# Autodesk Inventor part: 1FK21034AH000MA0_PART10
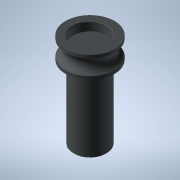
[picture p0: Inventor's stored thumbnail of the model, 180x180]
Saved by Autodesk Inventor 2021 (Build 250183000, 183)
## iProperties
Created: 2025-04
Part Number: 1FK21034AH000MA0_PART10
Material: Generic
Catalog Web Link: www.3dfindit.com
Description: -Servo synchronous motor
Document SubType Name: Modeling
Designer: psAdmin
Mass: 6.43867 g
Surface Area: 29.6592 cm^2
Volume: 6.43867 cm^3
Density: 1 g/cm^3
Appearance: PSOLRGB-212-217-219
Category: PARTsolutions
Title: 1FK21034AH000MA0_PART10
Author: Cadenas PARTsolutions
Comments: Servo synchronous motor
Sending System: PARTsolutions
Preprocessor: ST-DEVELOPER v19.3
PSOL_IDENT_0: {$CADENAS_DATA/23d-libs/siemens_ag/_cat_/ec/b7/1fk21034ah000ma0.prj},216 {VTYP=3D},{NB=1FK21034AH000
PSOL_IDENT_1: MA0_PART10},{LINA=1FK21034AH000MA0_PART10},{NN=1FK21034AH000MA0_PART10},{NOPRJ=TRUE},{DATE=19.08.202
PSOL_IDENT_2: 5 14:01:05},{GEOMDATE=30.07.2025 02:01:02},{VERSION=},{LINEID=10},{WBVAR=},{WBNUMERIC=}  {NB=1FK2103
PSOL_IDENT_3: 4AH000MA0_PART10},{LINA=1FK21034AH000MA0_PART10},{KT=DUMMY},{PREVIEW=../../../_pool_/7c/50/p_d211_xx
PSOL_IDENT_4: _00932j.png},{DESCSHORT=SIMOTICS S-1FK2 HD, SINAMICS S210 3AC 400V-480V, 1.01 Nm, 4500 rpm},{DESCLON
PSOL_IDENT_5: G=SIMOTICS S-1FK2 HD servo motor M0=1.27 Nm; PN = 0.48 kW at nN=4500 rpm (380-480 V); PN = 0.3 kW at
PSOL_IDENT_6: nN=2500 rpm (200-240 V); degree of protection IP64; cylindrical shaft D14 x 30 mm; absolute encoder
PSOL_IDENT_7: 22-bit + 12-bit multiturn (encoder AM22DQC); with OCC interface; plug size M17, rotatable; SIMOTICS
PSOL_IDENT_8: S-1FK2 servomotorfor a wide range of uses in industrial environments. SIMOTICS S‑1FK2 servomotors a
PSOL_IDENT_9: re compact synchronous motors with a high dynamic performance that set themselves apart as a result
PSOL_IDENT_10: of their high power density, degree of protection and overload capability. The motors are available
PSOL_IDENT_11: in two variants: as High Dynamic variant (highest dynamic performance as a result of the low intrins
PSOL_IDENT_12: ic moment of inertia for applications demanding a high dynamic performance with low moved masses) -
PSOL_IDENT_13: and as Compact variant (precise and stable closed-loop control for medium up to large moved masses a
PSOL_IDENT_14: s a result of a medium intrinsic moment of inertia). SIMOTICSS‑1FK2 servomotors fully exploit their
PSOL_IDENT_15: strengths in a system with the SINAMICSS210 frequency converter and simple connection using the one
PSOL_IDENT_16: cable connection (OCC). Advantages include the short control and positioning times, fast and precise
PSOL_IDENT_17: correction of disturbing quantities as well as stable control with a high dynamic performance. The
PSOL_IDENT_18: servo motors can be configured to address a wide range of requirements. For example with and without
PSOL_IDENT_19: holding brake, IP64 or IP65 degree of protection, singleturn or multiturn absolute encoders - to na
PSOL_IDENT_20: me just a few. Further, the servomotors are available in different shaft heights extending from 20 t
PSOL_IDENT_21: o 100. A shaft sealing ring is available to achieve an IP65 degree of protection and for subsequent
PSOL_IDENT_22: mounting at the motor or as spare part. SIMOTICS - the optimum motor for each and every motion contr
PSOL_IDENT_23: ol application.},{INTNO=4034106444822},{SUPPLIERALTNO=1FK2103-4AH00-0MA0},{MANUID=1FK21034AH000MA0},
PSOL_IDENT_24: {MANUNAME=Siemens},{MANUTYPEDESC=SYNCHRONOUS MOTOR 1FK2 HD 1,27 NM},{AAU732=SIMOTICS},{AAO057=S-1FK2
PSOL_IDENT_25: },{AAU734=SIMOTICS S-1FK2 HD servo motor M0=1.27 Nm; PN = 0.48 kW at nN=4500 rpm (380-480 V); PN = 0
PSOL_IDENT_26: .3 kW at nN=2500 rpm (200-240 V); degree of protection IP64; cylindrical shaft D14 x 30 mm; absolute
PSOL_IDENT_27: encoder 22-bit + 12-bit multiturn (encoder AM22DQC); with OCC interface; plug size M17, rotatable;}
PSOL_IDENT_28: ,{AAW338=SYNCHRONOUS MOTOR 1FK2 HD 1,27 NM},{AAO742=SIMOTICS},{AAO663=4034106444822},{NOCUPEROU=1},{
PSOL_IDENT_29: PRICEQUANTITY=1},{QUANTITYMIN=1},{QUANTITYINT=1},{CTN=85015100},{COO=RO},{AAO676=1FK2103-4AH00-0MA0}
PSOL_IDENT_30: ,{AAO677=Siemens AG},{ORDERUNIT=C62},{CONTENTUNIT=C62}
NB: 1FK21034AH000MA0_PART10
NT: Servo synchronous motor
NBSYN: $MANUID._PART10
LINA: 1FK21034AH000MA0_PART10
CATALOG: SIEMENS
PREVIEW: ../../../_pool_/7c/50/p_d211_xx_00932j.png
DESCSHORT: SIMOTICS S-1FK2 HD, SINAMICS S210 3AC 400V-480V, 1.01 Nm, 4500 rpm
DESCLONG: SIMOTICS S-1FK2 HD servo motor M0=1.27 Nm; PN = 0.48 kW at nN=4500 rpm (380-480 V); PN = 0.3 kW at nN=2500 rpm (200-240 V); degree of protection IP64; cylindric
INTNO: 4034106444822
SUPPLIERALTNO: 1FK2103-4AH00-0MA0
MANUID: 1FK21034AH000MA0
MANUNAME: Siemens
MANUTYPEDESC: SYNCHRONOUS MOTOR 1FK2 HD 1,27 NM
AAU732: SIMOTICS
AAO057: S-1FK2
AAU734: SIMOTICS S-1FK2 HD servo motor M0=1.27 Nm; PN = 0.48 kW at nN=4500 rpm (380-480 V); PN = 0.3 kW at nN=2500 rpm (200-240 V); degree of protection IP64; cylindric
AAW338: SYNCHRONOUS MOTOR 1FK2 HD 1,27 NM
AAO742: SIMOTICS
AAO663: 4034106444822.0
NOCUPEROU: 1
PRICEQUANTITY: 1
QUANTITYMIN: 1
QUANTITYINT: 1
CTN: 85015100
COO: RO
ARTICLENO: 1FK21034AH000MA0_PART10
BOMINFO: 1FK21034AH000MA0_PART10
CREATOR: CADENAS GmbH
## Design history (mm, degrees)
feature "2025_04_17_15_01_37_0314"
body "Solid1"
